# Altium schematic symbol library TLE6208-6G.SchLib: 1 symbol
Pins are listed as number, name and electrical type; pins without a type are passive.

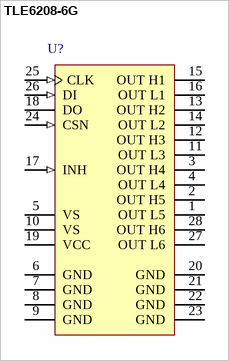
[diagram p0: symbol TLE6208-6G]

## TLE6208-6G
designator U?
Hex-Half-Bridge / Double Six-Driver, -40 to 150 degC, PG-DSO-28-24, Reel, Green; Manufacturer: Infineon; PartNumber: TLE6208-6G; Green: TRUE; Group: Multi Half Bridges; IPeak: 6 x 1 A; Iq: 6 x 0.6 A; Iq (typ): 10 uA; Protect: short circuit e.a.
footprint INF-PG-DSO-28-24_N (SOP, 28-Leads, Body 17.9x7.5mm, Pitch 1.27mm, IPC Medium Density)
footprint INF-PG-DSO-28-24_L (SOP, 28-Leads, Body 17.9x7.5mm, Pitch 1.27mm, IPC High Density)
footprint INF-PG-DSO-28-24_M (SOP, 28-Leads, Body 17.9x7.5mm, Pitch 1.27mm, IPC Low Density)
pins: 1 OUT L5 (hiz) "Low-Side-Output 5; Power-MOS open drain with internal reverse diode; no internal clamp diode or active zenering; short circuit protected and open load controlled.", 2 OUT H5 (hiz) "High-Side-Output 5; Power-MOS open source with internal reverse diode; no internal clamp diode or active zenering; short circuit protected and open load controlled.", 3 OUT H4 (hiz) "High-Side-Output 4; see pin2.", 4 OUT L4 (hiz) "Low-Side-Output 4; see pin1.", 5 VS (power) "Power supply; external connection to pin 10 necessary; needs a blocking capacitor as close as possible to GND Value: 22 uF electrolytic in parallel to 220 nF ceramic.", 6 GND (power) "Ground; Reference potential; internal connection to pin 20, 21, 22 and 23; cooling tab; to reduce thermal resistance; place cooling areas on PCB close to this pins.", 7 GND (power) "Ground; Reference potential; internal connection to pin 20, 21, 22 and 23; cooling tab; to reduce thermal resistance; place cooling areas on PCB close to this pins.", 8 GND (power) "Ground; Reference potential; internal connection to pin 20, 21, 22 and 23; cooling tab; to reduce thermal resistance; place cooling areas on PCB close to this pins.", 9 GND (power) "Ground; Reference potential; internal connection to pin 20, 21, 22 and 23; cooling tab; to reduce thermal resistance; place cooling areas on PCB close to this pins.", 10 VS (power) "Power Supply; see pin 5.", 11 OUT L3 (hiz) "Low-Side-Output 3; see pin1.", 12 OUT H3 (hiz) "High-Side-Output 3; see pin2.", 13 OUT H2 (hiz) "High-Side-Output 2; see pin2.", 14 OUT L2 (hiz) "Low-Side-Output 2; see pin1.", 15 OUT H1 (hiz) "High-Side-Output 1; see pin2.", 16 OUT L1 (hiz) "Low-Side-Output 1; see pin1.", 17 INH (in) "Inhibit input; has an internal pull down; device is switched in standby condition by pulling the INH terminal low.", 18 DO (hiz) "Serial-Data-Output; this 3-state output transfers diagnosis data to the control device; the output will remain 3-stated unless the device is selected by a low on Chip-Select-Not (CSN); see Table 2 for Diagnosis protocol.", 19 VCC (power) "Logic supply voltage; needs a blocking capacitor as close as possible to GND; Value: 10 uF electrolytic in parallel to 220 nF ceramic.", 20 GND (power) "Ground", 21 GND (power) "Ground", 22 GND (power) "Ground", 23 GND (power) "Ground", 24 CSN (in) "Chip-Select-Not input; CSN is an active low input; serial communication is enabled by pulling the CSN terminal low; CSN input should only be transitioned when CLK is low; CSN has an internal active pull up and requires CMOS (See Datasheet)", 25 CLK (in) "Serial clock input; clocks the shiftregister; CLK has an internal active pull down and requires CMOS logic level inputs.", 26 DI (in) "Serial data input; receives serial data from the control device; serial data transmitted to DI is an 16bit control word with the Least Significant Bit (LSB) being transferred first: the input has an active pull down and (See Datasheet)", 27 OUT L6 (hiz) "Low-Side-Output 6; see pin1.", 28 OUT H6 (hiz) "High-Side-Output 6; see pin2."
